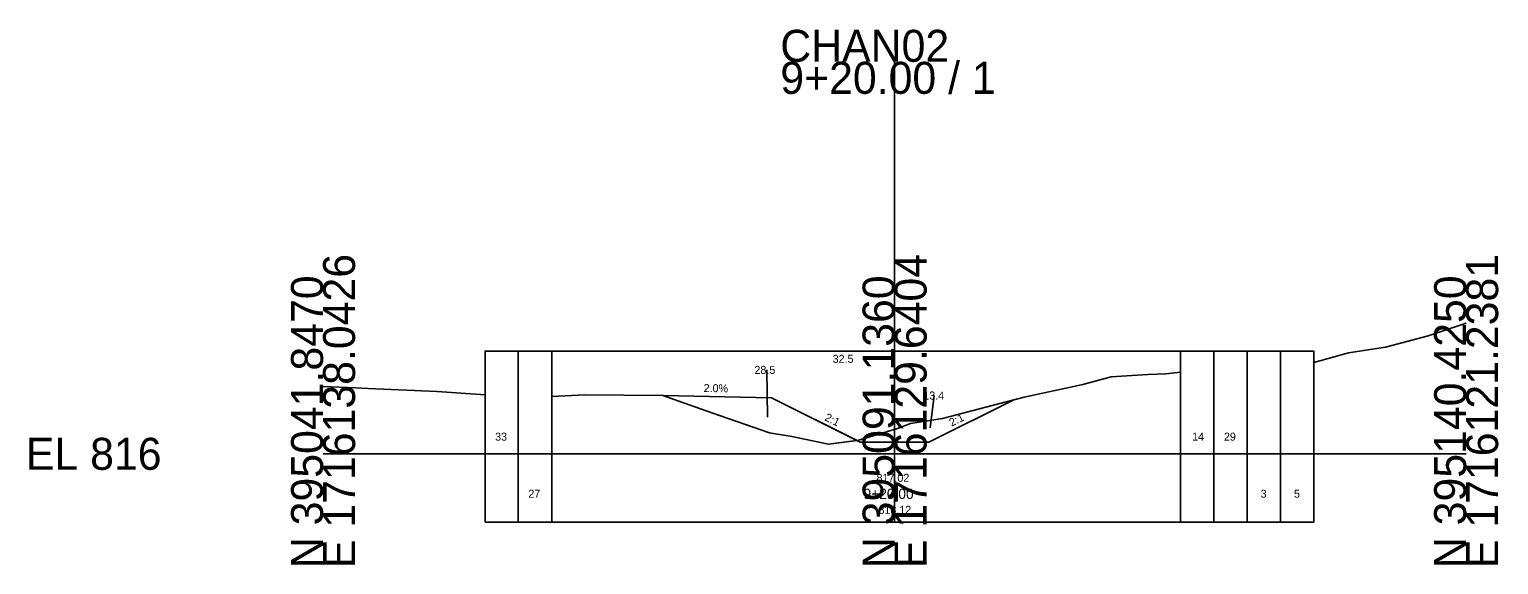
# Model space of a CAD drawing. Extents: x -26 to 103, y -10 to 16052.
# Drawn here: x -25.7 to 102.8, y 2490.3 to 2537.1 of the extents above; entities that cross this region are included whole.
import ezdxf

# ---------------------------------------------------------------- set-up
doc = ezdxf.new("R2010")
doc.units = 0
for name, color, linetype in [('GK_Cells', 7, 'Continuous'), ('SH_Text', 7, 'Continuous'), ('XS_P_Annotation', 7, 'Continuous'), ('XS_P_Boundary', 7, 'Continuous'), ('XS_P_Earthwork_Shapes', 7, 'Continuous'), ('XS_P_Finished_Grade', 7, 'Continuous'), ('XS_X_Ground_Line', 7, 'Continuous')]:
    doc.layers.add(name, color=color, linetype=linetype)

msp = doc.modelspace()

# ---------------------------------------------------------------- linework, layer by layer
at = {"layer": 'GK_Cells'}
for p, q in [((50, 2500), (50, 2534.29)), ((0, 2500), (50, 2500)), ((50, 2500), (100, 2500))]:
    msp.add_line(p, q, dxfattribs=at)
at = {"layer": 'XS_P_Boundary'}
for p, q in [((17.08, 2494.01), (17.08, 2508.99)), ((20, 2494.01), (20, 2508.99)), ((50, 2494.01), (50, 2508.99)), ((75, 2494.01), (75, 2508.99)), ((77.92, 2494.01), (77.92, 2508.99)), ((80.83, 2494.01), (80.83, 2508.99)), ((83.75, 2494.01), (83.75, 2508.99)), ((15.63, 2501.5), (15.63, 2501.5)), ((76.46, 2501.5), (76.46, 2501.5)), ((79.38, 2501.5), (79.38, 2501.5)), ((18.54, 2496.51), (18.54, 2496.51)), ((82.29, 2496.51), (82.29, 2496.51)), ((85.21, 2496.51), (85.21, 2496.51))]:
    msp.add_line(p, q, dxfattribs=at)
msp.add_lwpolyline([(14.17, 2494.01), (14.17, 2508.99), (86.67, 2508.99), (86.67, 2494.01)], close=True, dxfattribs=at)
at = {"layer": 'XS_P_Earthwork_Shapes'}
for p, q in [((38.87, 2503.21), (38.83, 2507.34)), ((39.23, 2504.9), (29.72, 2505.09)), ((46.72, 2501.16), (39.23, 2504.9)), ((53, 2501.02), (60.43, 2504.73)), ((53.12, 2502.27), (53.47, 2505.1)), ((60.43, 2504.73), (54.18, 2503.1)), ((46.72, 2501.16), (47, 2501.02)), ((47, 2501.02), (53, 2501.02))]:
    msp.add_line(p, q, dxfattribs=at)
for points in [[(29.72, 2505.09), (34.02, 2503.59), (39.05, 2501.83), (41.02, 2501.5), (44.23, 2500.84), (45.35, 2500.98), (46.72, 2501.16)], [(29.72, 2505.09), (39.23, 2504.9), (47, 2501.02), (53, 2501.02), (60.43, 2504.73)], [(54.18, 2503.1), (51.4, 2502.64), (50.26, 2502.21), (46.88, 2501.18), (46.72, 2501.16)]]:
    msp.add_lwpolyline(points, dxfattribs=at)
at = {"layer": 'XS_P_Finished_Grade'}
for p, q in [((39.23, 2504.9), (29.72, 2505.09)), ((39.23, 2504.9), (47, 2501.02)), ((60.43, 2504.73), (53, 2501.02)), ((47, 2501.02), (53, 2501.02))]:
    msp.add_line(p, q, dxfattribs=at)
at = {"layer": 'XS_X_Ground_Line'}
for points in [[(86.67, 2507.99), (89.7, 2508.82), (92.93, 2509.34), (96.68, 2510.31), (100, 2511.43)], [(20, 2505.02), (22.91, 2505.15), (29.72, 2505.09), (34.02, 2503.59), (39.05, 2501.83), (41.02, 2501.5), (44.23, 2500.84), (45.35, 2500.98), (46.88, 2501.18), (50.26, 2502.21), (51.4, 2502.64), (54.18, 2503.1), (61.32, 2504.96), (66.47, 2506.05), (68.94, 2506.73), (72.14, 2506.95), (73.72, 2507), (75, 2507.13)], [(0, 2505.89), (2.83, 2505.77), (3.93, 2505.72), (8, 2505.53), (8.61, 2505.5), (9.98, 2505.44), (14.17, 2505.17)]]:
    msp.add_lwpolyline(points, dxfattribs=at)

# ---------------------------------------------------------------- texts
at = {"layer": 'GK_Cells'}
for s, p in [('CHAN02', (40, 2534.29)), ('9+20.00 / 1', (40, 2531.49)), ('EL 816', (-26, 2498.6))]:
    msp.add_text(s, height=2.8, dxfattribs=at).set_placement(p)
for s, p in [('E 1716138.0426', (2.8, 2490)), ('E 1716129.6404', (52.8, 2490)), ('E 1716121.2381', (102.8, 2490)), ('N 395041.8470', (0, 2490)), ('N 395091.1360', (50, 2490)), ('N 395140.4250', (100, 2490))]:
    msp.add_text(s, height=2.8, rotation=90, dxfattribs=at).set_placement(p)
at = {"layer": 'SH_Text'}
for s, p in [('33', (15.05, 2501.15)), ('14', (76.03, 2501.15)), ('29', (78.81, 2501.15)), ('27', (17.96, 2496.16)), ('3', (82.02, 2496.16)), ('5', (84.94, 2496.16))]:
    msp.add_text(s, height=0.7, dxfattribs=at).set_placement(p)
at = {"layer": 'XS_P_Annotation'}
for s, rotation, p in [('2.0%', 358.8542, (33.29, 2505.41)), ('2:1', 333.4349, (43.82, 2502.96)), ('2:1', 26.5651, (54.99, 2502.37))]:
    msp.add_text(s, height=0.7, rotation=rotation, dxfattribs=at).set_placement(p)
for s, height, p in [('817.02', 0.7, (48.42, 2497.55)), ('9+20.00', 0.9, (47.28, 2496.05)), ('818.12', 0.7, (48.59, 2494.75))]:
    msp.add_text(s, height=height, dxfattribs=at).set_placement(p)
at = {"layer": 'XS_P_Earthwork_Shapes'}
for s, p in [('28.5', (37.74, 2506.99)), ('32.5', (44.58, 2507.96)), ('13.4', (52.51, 2504.75))]:
    msp.add_text(s, height=0.7, dxfattribs=at).set_placement(p)

doc.saveas('drawing.dxf')
